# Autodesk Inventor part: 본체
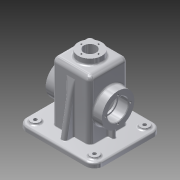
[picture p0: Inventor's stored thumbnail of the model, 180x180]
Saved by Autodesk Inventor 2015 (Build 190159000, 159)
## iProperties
Created: 2016-02
Part Number: 본체
Material: 알루미늄 6061
Document SubType Name: Modeling
Designer: Administrator
Density: 2.7 g/cm^3
Appearance: 알루미늄 - 평지
Mass: 799.421 g
Surface Area: 907.841 cm^2
Volume: 296.082 cm^3
Author: Administrator
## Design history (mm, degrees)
sketch "스케치1"
  geometry: L1 (-65, 57.5)-(65, 57.5); L2 (65, 57.5)-(65, -57.5); L3 (65, -57.5)-(-65, -57.5); L4 (-65, -57.5)-(-65, 57.5); L5 (-65, 57.5)-(65, -57.5); L6 (65, 57.5)-(-65, -57.5); 1 further point
  constraints: 12 end point, 2 midpoint, 2 parallel, 1 horizontal, 1 perpendicular
  dimensions: "d0" = 130 distance of L2.end L3.end; "d1" = 115 distance of L1.end L2.end
extrude "돌출1" new body sketch "스케치1" distance "d2" = 8; taper "d3" = 0 deg
sketch "스케치2"
  geometry: L1 (-32.5, 32.5)-(32.5, 32.5); L2 (32.5, 32.5)-(32.5, -32.5); L3 (32.5, -32.5)-(-32.5, -32.5); L4 (-32.5, -32.5)-(-32.5, 32.5); L5 (-32.5, 32.5)-(32.5, -32.5); L6 (32.5, 32.5)-(-32.5, -32.5); 1 further point
  constraints: 12 end point, 2 midpoint, 2 parallel, 1 horizontal, 1 perpendicular
  dimensions: "d4" = 65 distance of L2.end L3.end; "d5" = 65 distance of L1.end L2.end
extrude "돌출2" join sketch "스케치2" distance "d6" = 100; taper "d7" = 0 deg
sketch "스케치5"
  geometry: C1 r 20 at (0, 0); 1 further point
  constraints: 1 centre point, 1 coincident
  dimensions: "d16" = 40 diameter of C1
extrude "돌출5" join sketch "스케치5" distance "d17" = 10; taper "d18" = 0 deg
sketch "스케치7"
  geometry: L1 (-42.5, 32.753)-(-42.5, 8); L2 (65, 8)-(-65, 8) reference; L3 (-42.5, 32.753)-(42.5, 32.753); L4 (42.5, 32.753)-(42.5, 8); L5 (-32.5, 8)-(-32.5, 108) reference; 3 further points
  constraints: 6 end point, 2 point on line, 1 horizontal, 1 perpendicular, 1 vertical
  dimensions: "d23" = 24.75313 distance of L1.start L1.end; "d25" = 42.5 horizontal distance of point (0, 0) L1.end; "d26" = 42.5 distance from line of L4 point (0, 0)
extrude "돌출6" join sketch "스케치7" stored distance "d27" = 6; taper "d28" = 0 deg
sketch "스케치10"
  geometry: C1 r 7.5 at (-50, -42.5); 1 further point
  constraints: 1 centre point
  dimensions: "d39" = 15 diameter of C1; "d40" = 50 horizontal distance of point (0, 0) C1.centre; "d41" = 42.5 vertical distance of point (0, 0) C1.centre
extrude "돌출9" join sketch "스케치10" distance "d42" = 3; taper "d43" = 0 deg
sketch "스케치12"
  geometry: L1 (-65, -57.5)-(-65, 57.5) reference; L2 (-65, 57.5)-(65, 57.5) reference; L3 (65, 57.5)-(65, -57.5) reference; L4 (65, -57.5)-(-65, -57.5) reference; L5 (-60, 52.5)-(-60, -52.5); L6 (-60, -52.5)-(60, -52.5); L7 (60, -52.5)-(60, 52.5); L8 (60, 52.5)-(-60, 52.5); 1 further point
  constraints: 8 end point, 3 other
  dimensions: "d51" = 5 distance between parallel lines of L1 L5
extrude "돌출10" join sketch "스케치12" distance "d52" = 2; taper "d53" = 0 deg
sketch "스케치13"
  geometry: L1 (110, -20)-(110, 85) reference; C1 r 27.5 at (55, 32.5); 1 further point
  constraints: 1 centre point, 1 horizontal alignment
  dimensions: "d54" = 55 diameter of C1; "d55" = 55 distance from line of L1 C1.centre
extrude "돌출11" join sketch "스케치13" distance "d56" = 15; taper "d57" = 0 deg
sketch "스케치14"
  geometry: L1 (-32.5, 93.069)-(-47.5, 8); L2 (-57.5, 0)-(-57.5, 8) reference; L3 (-57.5, 8)-(57.5, 8) reference; L4 (-32.5, 8)-(-32.5, 108) reference; L5 (-47.5, 8)-(-32.5, 8); 1 further point
  constraints: 4 end point, 1 collinear, 1 horizontal alignment, 1 point on line
  dimensions: "d58" = 10 distance from line of L2 L1.end; "d59" = 100 deg angle of L3 L1
extrude "돌출12" join sketch "스케치14" stored distance "d60" = 10; taper "d61" = 0 deg
sketch "스케치15"
  geometry: L1 (27.5, 27.5)-(-27.5, 27.5); L2 (-27.5, 27.5)-(-27.5, -27.5); L3 (-27.5, -27.5)-(27.5, -27.5); L4 (27.5, -27.5)-(27.5, 27.5); L5 (27.5, 27.5)-(-27.5, -27.5); L6 (-27.5, 27.5)-(27.5, -27.5); 1 further point
  constraints: 12 end point, 2 midpoint, 2 parallel, 1 horizontal, 1 perpendicular
  dimensions: "d62" = 55 distance of L3.end L2.end; "d63" = 55 distance of L1.end L2.end
extrude "돌출13" cut sketch "스케치15" distance "d64" = 105; taper "d65" = 0 deg
sketch "스케치16"
  geometry: C1 r 7.5 at (0, 0) reference; 2 further points
  constraints: 1 coincident
hole "구멍2" sketch "스케치16" at (0, 0) diameter "d66" = 6; stored, may be unused: countersink angle "d70" = 90 deg, drill point angle "d72" = 118 deg; dims "d67" = 6, "d68" = 4, "d69" = 2, "d71" = 8
sketch "스케치20"
  geometry: C1 r 10.5 at (0, 0); 1 further point
  constraints: 1 centre point, 1 coincident
  dimensions: "d96" = 21 diameter of C1
extrude "돌출16" cut sketch "스케치20" stored distance "d97" = 3; taper "d98" = 0 deg
sketch "스케치21"
  geometry: 2 further points
  constraints: 1 vertical alignment
  dimensions: "d99" = 14.5 distance of point (0, 0) point (0, -14.5)
hole "구멍4" sketch "스케치21" at (0, -14.5) diameter "d100" = 2.459; stored, may be unused: countersink angle "d104" = 90 deg, drill point angle "d106" = 118 deg; dims "d101" = 7, "d102" = 4, "d103" = 2, "d105" = 9
fillet "모깎기2" dims "d110" = 15
fillet "모깎기3" dims "d111" = 10
sketch "스케치22"
  geometry: C1 r 27.5 at (0, 0) reference; C2 r 17.5 at (0, 0); 1 further point
  constraints: 1 centre point, 1 coincident
  dimensions: "d113" = 35 diameter of C2
extrude "돌출17" cut sketch "스케치22" distance "d114" = 17; taper "d115" = 0 deg
sketch "스케치23"
  geometry: C1 r 17.5 at (0, 0) reference; C2 r 15 at (0, 0); 1 further point
  constraints: 1 centre point, 1 coincident
  dimensions: "d116" = 30 diameter of C2
extrude "돌출18" cut sketch "스케치23" distance "d117" = 3; taper "d118" = 0 deg
fillet "모깎기5" dims "d119" = 8
fillet "모깎기8" dims "d122" = 3
fillet "모깎기9" dims "d123" = 0.3
fillet "모깎기10" dims "d124" = 3
fillet "모깎기12" dims "d126" = 3
fillet "모깎기13" dims "d130" = 8
sketch "스케치24"
  geometry: C1 r 17.5 at (0, 0) reference; C2 r 27.5 at (0, 0) reference; 2 further points
  constraints: 1 horizontal alignment
  dimensions: "d136" = 21 distance of C1.centre point (-21, 0)
hole "구멍5" sketch "스케치24" at (-21, 0) diameter "d137" = 3.242; stored, may be unused: countersink angle "d141" = 90 deg, drill point angle "d143" = 118 deg; dims "d138" = 8, "d139" = 4, "d140" = 2, "d142" = 10
node "작업 평면1"
sketch "스케치25"
  geometry: L1 (47, 32.5)-(-45, 32.5) reference; L2 (65, -20)-(65, 20) reference; 3 further points
  constraints: 1 other
  dimensions: "d148" = 32.5 distance from line of L1 point (39, 0); "d149" = 26 distance from line of point (39, 0) L2
feature "엠보싱1" sketch "스케치25" dims "d150" = 0.5, "d151" = 0
fillet "모깎기16" dims "d152" = 3
fillet "모깎기17" dims "d153" = 5
fillet "모깎기18" dims "d154" = 1
chamfer "모따기3" distance "d155" = 1; stored, may be unused: second distance "d156" = 2, angle "d157" = 45 deg
fillet "모깎기19" dims "d158" = 3
chamfer "모따기4" distance "d159" = 1; stored, may be unused: second distance "d160" = 2, angle "d161" = 45 deg
node "솔리드1"
mirror "대칭3"
mirror "대칭4"
pattern_linear "직사각형 패턴1" dims "d78" = 85
pattern_circular "원형 패턴2" dims angle "d108" = 360 deg
mirror "대칭7"
pattern_circular "원형 패턴3" dims angle "d145" = 360 deg
mirror "대칭8"
node "투영된 루프2"
node "투영된 루프6"
node "투영된 루프7"
node "투영된 루프8"
node "절단 모서리 투영3"
